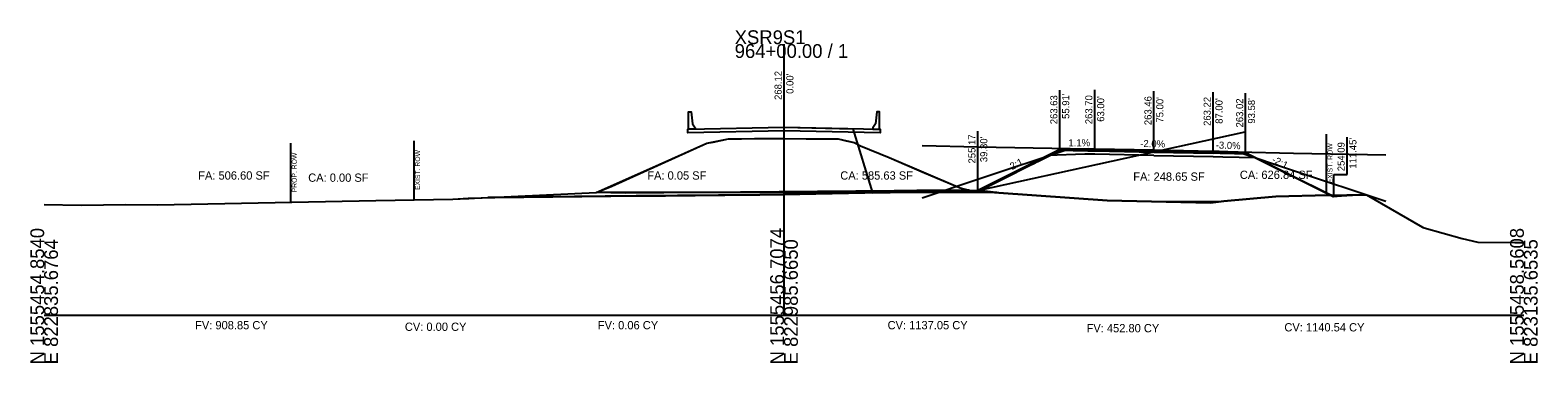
# Model space of a CAD drawing. Extents: x -26 to 823017, y -16 to 1558356.
# Drawn here: x 997.2 to 1302.8, y 3490.3 to 3557.8 of the extents above; entities that cross this region are included whole.
import ezdxf

# ---------------------------------------------------------------- set-up
doc = ezdxf.new("R2010")
doc.units = 0
for name, color, linetype in [('ASPHALT_19MM1', 7, 'Continuous'), ('CONST_DCH', 7, 'Continuous'), ('CONST_LV3', 7, 'Continuous'), ('Default', 7, 'Continuous'), ('Draft_XS_Grid', 7, 'Continuous'), ('DTM_CORRIDOR', 7, 'Continuous'), ('DTM_P_FINISHED_GRADE2', 7, 'Continuous'), ('DTM_TEMP_DROP', 7, 'Continuous'), ('DTM_X_GROUND', 7, 'Continuous'), ('PROFILES_DCH_2', 7, 'Continuous'), ('SLOPE_STAKES_FILL', 7, 'Continuous'), ('XS_CELL', 7, 'Continuous'), ('XS_M_SHAPES_EARTHWORK', 7, 'Continuous'), ('XS_P_ASPHALT', 7, 'Continuous'), ('XS_P_CONCRETE', 7, 'Continuous'), ('XS_P_DR_GRAVEL', 7, 'Continuous'), ('XS_P_GROUND', 7, 'Continuous'), ('XS_P_NULL_POINT', 7, 'Continuous'), ('XS_P_ROW', 7, 'Continuous'), ('XS_P_SHOULDER', 7, 'Continuous'), ('XS_P_SUBGRADE_GRANULAR', 7, 'Continuous'), ('XS_P_SUBGRADE_UNDERCUT', 7, 'Continuous'), ('XS_P_TX_CLEARZONE', 7, 'Continuous'), ('XS_P_TX_FS_BS', 7, 'Continuous'), ('XS_SHEET_EW_TX_AREA', 7, 'Continuous'), ('XS_SHEET_EW_TX_VOLUME', 7, 'Continuous'), ('XS_X_ROW', 7, 'Continuous')]:
    doc.layers.add(name, color=color, linetype=linetype)

msp = doc.modelspace()

# ---------------------------------------------------------------- linework, layer by layer
at = {"layer": 'ASPHALT_19MM1'}
msp.add_lwpolyline([(1213, 3533.33), (1225, 3533.09), (1237, 3532.85), (1237, 3533.05), (1225, 3533.29), (1213, 3533.53), (1213, 3533.33)], dxfattribs=at)
at = {"layer": 'CONST_DCH'}
msp.add_lwpolyline([(1213, 3533.53), (1225, 3533.29), (1237, 3533.05), (1237, 3533.22), (1225, 3533.46), (1213, 3533.7), (1213, 3533.53)], dxfattribs=at)
at = {"layer": 'CONST_LV3'}
for points in [[(1150, 3538.12), (1164, 3537.84)], [(1168, 3524.85), (1168, 3524.85), (1164, 3537.84)], [(1189.3, 3525.32), (1243.53, 3537.18), (1243.53, 3537.18)], [(1178, 3534.4), (1189.31, 3534.18), (1208, 3533.8), (1214.41, 3533.67), (1225, 3533.46), (1235.59, 3533.25), (1242, 3533.12), (1253.31, 3532.9), (1272, 3532.52)], [(1178, 3523.8), (1189.31, 3527.57), (1208, 3533.8), (1214.41, 3533.67), (1225, 3533.46), (1235.59, 3533.25), (1242, 3533.12), (1253.31, 3529.35), (1272, 3523.12)], [(1189.3, 3525.32), (1201.35, 3531.35), (1205.91, 3533.63), (1211.75, 3533.72), (1213, 3533.7)], [(1189.6, 3525.26), (1191.43, 3526.18), (1197.16, 3529.04), (1197.23, 3529.08), (1197.34, 3529.13), (1199.63, 3530.28), (1200.92, 3530.92), (1200.94, 3530.93), (1201.12, 3531.02), (1201.47, 3531.2), (1205.91, 3533.42), (1211.75, 3533.65), (1213, 3533.7), (1222.01, 3533.52), (1225, 3533.46), (1234.01, 3533.28), (1237, 3533.22), (1238.25, 3533.17), (1243.58, 3532.96), (1248.25, 3530.63), (1250.7, 3529.4), (1259.83, 3524.84), (1261.33, 3524.09), (1263, 3524.22), (1264.08, 3524.27), (1266.38, 3524.42), (1268.1, 3524.44), (1279.43, 3517.88), (1279.55, 3517.81), (1279.64, 3517.75), (1279.8, 3517.7), (1287.5, 3515.52), (1290.66, 3514.78), (1298.15, 3514.73), (1300, 3514.73)], [(1243.58, 3533.02), (1260.98, 3524.33)], [(1000, 3522.45), (1007.51, 3522.34), (1016.53, 3522.43), (1022.97, 3522.39), (1067.25, 3523.26), (1082.86, 3523.53), (1085.83, 3523.69), (1086.06, 3523.71), (1086.16, 3523.71), (1086.29, 3523.72), (1087.28, 3523.76), (1089.93, 3523.88)]]:
    msp.add_lwpolyline(points, dxfattribs=at)
at = {"layer": 'Default'}
msp.add_lwpolyline([(1187.49, 3525.35), (1187.19, 3525.34), (1176.92, 3525.26), (1175.41, 3525.24), (1172.34, 3525.22), (1117.88, 3524.78), (1111.93, 3524.86)], dxfattribs=at)
at = {"layer": 'DTM_P_FINISHED_GRADE2'}
msp.add_lwpolyline([(1089.93, 3523.88), (1090.73, 3523.89), (1091.01, 3523.89), (1091.35, 3523.89), (1114.88, 3524.13), (1120.33, 3524.18), (1126, 3524.24), (1150, 3524.48), (1156.45, 3524.63), (1189.6, 3525.26)], dxfattribs=at)
at = {"layer": 'DTM_X_GROUND'}
for points in [[(1000, 3522.45), (1007.51, 3522.34), (1016.53, 3522.43), (1022.97, 3522.39), (1067.25, 3523.26), (1082.86, 3523.53), (1086.06, 3523.71), (1086.16, 3523.71), (1087.28, 3523.76), (1090.35, 3523.9), (1111.93, 3524.86), (1115.08, 3526.2), (1134.32, 3534.88), (1135.67, 3535.12), (1138.77, 3535.8), (1144.04, 3535.82), (1149.78, 3535.84), (1159.14, 3535.76), (1160.97, 3535.75), (1160.97, 3535.75), (1162.57, 3535.4), (1164.2, 3535.03), (1165.49, 3534.39), (1171.33, 3532), (1185.7, 3525.82), (1187.67, 3525.3), (1193.53, 3524.83), (1215.49, 3523.25), (1236.44, 3522.77), (1239.16, 3523.13), (1249.74, 3524.05), (1260.36, 3524.34), (1264.08, 3524.39), (1268.1, 3524.44), (1279.43, 3517.88), (1279.55, 3517.81), (1279.64, 3517.75), (1279.8, 3517.7), (1287.5, 3515.52), (1290.66, 3514.78), (1298.15, 3514.73), (1300, 3514.73)], [(1000, 3522.45), (1007.51, 3522.34), (1016.53, 3522.43), (1022.97, 3522.39), (1067.25, 3523.26), (1082.86, 3523.53), (1086.06, 3523.71), (1086.16, 3523.71), (1087.28, 3523.76), (1090.35, 3523.9), (1111.93, 3524.86), (1115.08, 3526.2), (1134.32, 3534.88), (1135.67, 3535.12), (1138.77, 3535.8), (1144.04, 3535.82), (1149.78, 3535.84), (1159.14, 3535.76), (1160.97, 3535.75), (1160.97, 3535.75), (1162.57, 3535.4), (1164.2, 3535.03), (1165.49, 3534.39), (1171.33, 3532), (1185.7, 3525.82), (1187.49, 3525.35), (1187.67, 3525.34), (1189.6, 3525.26), (1197.34, 3529.13), (1201.12, 3531.02), (1201.47, 3531.2), (1205.91, 3533.42), (1211.75, 3533.65), (1213, 3533.7), (1222.01, 3533.52), (1225, 3533.46), (1234.01, 3533.28), (1237, 3533.22), (1238.25, 3533.17), (1243.58, 3532.96), (1248.25, 3530.63), (1250.7, 3529.4), (1259.83, 3524.84), (1261.33, 3524.09), (1263, 3524.22), (1264.08, 3524.27), (1266.38, 3524.42), (1268.1, 3524.44), (1279.43, 3517.88), (1279.55, 3517.81), (1279.64, 3517.75), (1279.8, 3517.7), (1287.5, 3515.52), (1290.66, 3514.78), (1298.15, 3514.73), (1300, 3514.73)], [(1000, 3522.45), (1007.51, 3522.34), (1016.53, 3522.43), (1022.97, 3522.39), (1067.25, 3523.26), (1082.86, 3523.53), (1085.83, 3523.69), (1086.06, 3523.7), (1086.16, 3523.71), (1086.29, 3523.72), (1087.28, 3523.76), (1089.93, 3523.88), (1090.2, 3523.88), (1090.29, 3523.88), (1090.63, 3523.89), (1090.73, 3523.89), (1090.8, 3523.89), (1090.86, 3523.89), (1091.01, 3523.89), (1091.35, 3523.89), (1114.88, 3524.13), (1120.33, 3524.18), (1126, 3524.24), (1150, 3524.48), (1156.45, 3524.63), (1189.6, 3525.26), (1191.43, 3526.18), (1197.16, 3529.04), (1197.23, 3529.08), (1197.34, 3529.13), (1199.63, 3530.28), (1200.92, 3530.92), (1200.94, 3530.93), (1201.12, 3531.02), (1201.47, 3531.2), (1205.91, 3533.42), (1211.75, 3533.65), (1213, 3533.7), (1222.01, 3533.52), (1225, 3533.46), (1234.01, 3533.28), (1237, 3533.22), (1238.25, 3533.17), (1243.58, 3532.96), (1248.25, 3530.63), (1250.7, 3529.4), (1259.83, 3524.84), (1261.33, 3524.09), (1263, 3524.22), (1264.08, 3524.27), (1266.38, 3524.42), (1268.1, 3524.44), (1279.43, 3517.88), (1279.55, 3517.81), (1279.64, 3517.75), (1279.8, 3517.7), (1287.5, 3515.52), (1290.66, 3514.78), (1298.15, 3514.73), (1300, 3514.73)]]:
    msp.add_lwpolyline(points, dxfattribs=at)
at = {"layer": 'XS_CELL'}
for p, q in [((1150, 3500), (1150, 3555)), ((1000, 3500), (1150, 3500)), ((1150, 3500), (1300, 3500))]:
    msp.add_line(p, q, dxfattribs=at)
at = {"layer": 'XS_M_SHAPES_EARTHWORK'}
for points in [[(1089.93, 3523.88), (1090.35, 3523.9), (1111.93, 3524.86), (1115.08, 3526.2), (1134.32, 3534.88), (1135.67, 3535.12), (1138.77, 3535.8), (1144.04, 3535.82), (1149.78, 3535.84), (1159.14, 3535.76), (1160.97, 3535.75), (1160.97, 3535.75), (1162.57, 3535.4), (1164.2, 3535.03), (1165.49, 3534.39), (1171.33, 3532), (1185.7, 3525.82), (1187.67, 3525.3), (1188.25, 3525.25), (1156.41, 3524.63), (1150, 3524.48), (1145.1, 3524.43), (1120, 3524.18), (1094.94, 3523.93)], [(1188.25, 3525.25), (1189.3, 3525.17), (1189.3, 3525.27)]]:
    msp.add_lwpolyline(points, close=True, dxfattribs=at)
at = {"layer": 'XS_P_CONCRETE'}
for points in [[(1130.67, 3537.74), (1130.67, 3541.24), (1131.17, 3541.26), (1131.42, 3538.85), (1132, 3538.01), (1132, 3537.76), (1130.67, 3537.74)], [(1169.33, 3537.74), (1169.33, 3541.24), (1168.83, 3541.26), (1168.58, 3538.85), (1168, 3538.01), (1168, 3537.76), (1169.33, 3537.74)], [(1150, 3538.12), (1169.33, 3537.74), (1169.5, 3537.73), (1169.5, 3536.98), (1150, 3537.37), (1130.5, 3536.98), (1130.5, 3537.73), (1130.67, 3537.74), (1150, 3538.12)]]:
    msp.add_lwpolyline(points, dxfattribs=at)
at = {"layer": 'XS_P_DR_GRAVEL'}
for points in [[(1211.75, 3533.72), (1205.91, 3533.63), (1205.75, 3533.54), (1205.61, 3533.47), (1211.59, 3533.35), (1213, 3533.33), (1213, 3533.61), (1213, 3533.7), (1211.75, 3533.72)], [(1238.25, 3533.19), (1243.58, 3533.02), (1243.77, 3532.93), (1244.23, 3532.7), (1238.44, 3532.82), (1237, 3532.85), (1237, 3533.13), (1237, 3533.22), (1238.25, 3533.19)]]:
    msp.add_lwpolyline(points, dxfattribs=at)
at = {"layer": 'XS_P_GROUND'}
for points in [[(1205.91, 3533.63), (1189.3, 3525.32)], [(1243.58, 3533.02), (1261.45, 3524.09)], [(1189.3, 3525.27), (1156.41, 3524.63), (1150, 3524.48)], [(1168, 3524.85), (1189.3, 3525.25), (1189.3, 3525.25)], [(1168, 3524.85), (1189.3, 3525.25), (1189.3, 3525.25)], [(1260.98, 3524.35), (1260.36, 3524.34), (1260.36, 3524.34), (1249.74, 3524.05), (1249.74, 3524.05), (1239.16, 3523.13), (1239.16, 3523.13), (1236.44, 3522.77), (1236.44, 3522.77), (1215.49, 3523.25), (1215.49, 3523.25), (1193.53, 3524.83), (1193.53, 3524.83), (1189.3, 3525.17)], [(1189.3, 3525.17), (1193.53, 3524.83), (1193.53, 3524.83), (1215.49, 3523.25), (1215.49, 3523.25), (1236.44, 3522.77), (1236.44, 3522.77), (1239.16, 3523.13), (1239.16, 3523.13), (1249.74, 3524.05), (1249.74, 3524.05), (1260.36, 3524.34), (1260.36, 3524.34), (1260.98, 3524.35)], [(1089.93, 3523.88), (1094.94, 3523.93), (1120, 3524.18)], [(1120, 3524.18), (1145.1, 3524.43), (1150, 3524.48)]]:
    msp.add_lwpolyline(points, dxfattribs=at)
at = {"layer": 'XS_P_ROW'}
msp.add_line((1050, 3522.92), (1050, 3534.92), dxfattribs=at)
at = {"layer": 'XS_P_SHOULDER'}
for points in [[(1205.91, 3533.63), (1211.75, 3533.72), (1213, 3533.7)], [(1243.58, 3533.02), (1238.25, 3533.19), (1237, 3533.22)]]:
    msp.add_lwpolyline(points, dxfattribs=at)
at = {"layer": 'XS_P_SUBGRADE_GRANULAR'}
for points in [[(1213, 3532.66), (1211, 3532.7), (1203.46, 3532.4)], [(1225, 3532.42), (1213, 3532.66)], [(1225, 3532.42), (1237, 3532.18)], [(1237, 3532.18), (1239, 3532.14), (1245.62, 3532.01)]]:
    msp.add_lwpolyline(points, dxfattribs=at)
at = {"layer": 'XS_P_SUBGRADE_UNDERCUT'}
for points in [[(1111.93, 3524.86), (1124.7, 3530.54), (1134.32, 3534.88), (1138.77, 3535.8), (1141.4, 3535.81), (1146.91, 3535.83), (1149.78, 3535.84), (1154.46, 3535.8), (1159.14, 3535.76), (1160.97, 3535.75), (1164.2, 3535.03), (1165.49, 3534.39), (1171.33, 3532), (1178.51, 3528.91), (1185.7, 3525.82), (1187.67, 3525.3), (1190.6, 3525.06), (1193.14, 3524.86)], [(1226.45, 3523), (1215.49, 3523.25), (1204.51, 3524.04), (1193.53, 3524.83), (1189.6, 3525.26), (1205.91, 3533.42), (1213, 3533.7), (1225, 3533.46), (1237, 3533.22), (1243.58, 3532.96), (1260.81, 3524.34), (1255.05, 3524.2), (1249.74, 3524.05), (1244.45, 3523.59), (1239.16, 3523.13), (1238.17, 3523)]]:
    msp.add_lwpolyline(points, close=True, dxfattribs=at)
at = {"layer": 'XS_P_TX_CLEARZONE'}
for p, q in [((1150, 3538.12), (1150, 3550.12)), ((1205.91, 3533.63), (1205.91, 3545.63)), ((1213, 3533.7), (1213, 3545.7)), ((1225, 3533.46), (1225, 3545.46)), ((1237, 3533.22), (1237, 3545.22)), ((1243.58, 3533.02), (1243.58, 3545.02)), ((1189.3, 3525.32), (1189.3, 3537.32)), ((1264.15, 3528.52), (1264.15, 3536.09)), ((1261.45, 3524.09), (1261.45, 3528.52)), ((1261.45, 3528.52), (1264.15, 3528.52))]:
    msp.add_line(p, q, dxfattribs=at)
at = {"layer": 'XS_X_ROW'}
for p, q in [((1260, 3524.75), (1260, 3536.75)), ((1075, 3523.39), (1075, 3535.39))]:
    msp.add_line(p, q, dxfattribs=at)

# ---------------------------------------------------------------- texts
at = {"layer": 'CONST_DCH'}
for p in [(1189.22, 3525.2), (1260.9, 3524.21), (1261.37, 3523.97)]:
    msp.add_text('X', height=0.24, dxfattribs=at).set_placement(p)
at = {"layer": 'Draft_XS_Grid'}
msp.add_text('-', height=0.0001, dxfattribs=at).set_placement((1000, 3500))
at = {"layer": 'DTM_CORRIDOR'}
for p in [(1212.92, 3533.58), (1224.92, 3533.34), (1236.92, 3533.1)]:
    msp.add_text('X', height=0.24, dxfattribs=at).set_placement(p)
at = {"layer": 'DTM_TEMP_DROP'}
for p in [(1149.92, 3538), (1189.22, 3525.05)]:
    msp.add_text('X', height=0.24, dxfattribs=at).set_placement(p)
at = {"layer": 'PROFILES_DCH_2'}
for p in [(1167.92, 3524.73), (1189.22, 3525.2), (1260.9, 3524.21)]:
    msp.add_text('X', height=0.24, dxfattribs=at).set_placement(p)
at = {"layer": 'SLOPE_STAKES_FILL'}
for p in [(1149.92, 3524.36), (1189.22, 3525.15), (1089.85, 3523.76)]:
    msp.add_text('X', height=0.24, dxfattribs=at).set_placement(p)
at = {"layer": 'XS_CELL'}
for s, p in [('XSR9S1', (1140, 3555)), ('964+00.00 / 1', (1140, 3552.2))]:
    msp.add_text(s, height=2.8, dxfattribs=at).set_placement(p)
for s, p in [('N 1555454.8540', (1000, 3490)), ('N 1555456.7074', (1150, 3490)), ('N 1555458.5608', (1300, 3490)), ('E 822835.6764', (1002.8, 3490)), ('E 822985.6650', (1152.8, 3490)), ('E 823135.6535', (1302.8, 3490))]:
    msp.add_text(s, height=2.8, rotation=90, dxfattribs=at).set_placement(p)
at = {"layer": 'XS_P_ASPHALT'}
for p in [(1189.22, 3525.2), (1261.37, 3523.97)]:
    msp.add_text('X', height=0.24, dxfattribs=at).set_placement(p)
at = {"layer": 'XS_P_NULL_POINT'}
msp.add_text('X', height=0.24, dxfattribs=at).set_placement((1189.22, 3525.15))
at = {"layer": 'XS_P_ROW'}
msp.add_text('PROP. ROW', height=1, rotation=90, dxfattribs=at).set_placement((1051.2, 3524.92))
at = {"layer": 'XS_P_SHOULDER'}
for p in [(1205.84, 3533.51), (1243.51, 3532.9), (1149.92, 3524.36)]:
    msp.add_text('X', height=0.24, dxfattribs=at).set_placement(p)
at = {"layer": 'XS_P_TX_CLEARZONE'}
for s, p in [('268.12', (1149.52, 3543.67)), ("0.00'", (1151.92, 3544.91)), ('263.63', (1205.43, 3538.74)), ("55.91'", (1207.83, 3539.82)), ('263.70', (1212.52, 3538.75)), ("63.00'", (1214.92, 3539.24)), ('263.46', (1224.52, 3538.56)), ("75.00'", (1226.92, 3539.07)), ('263.22', (1236.52, 3538.4)), ("87.00'", (1238.92, 3538.83)), ('263.02', (1243.1, 3538.09)), ("93.58'", (1245.5, 3538.86)), ('255.17', (1188.82, 3530.78)), ("39.30'", (1191.22, 3531.04)), ('254.09', (1263.67, 3529.21)), ("111.45'", (1266.07, 3529.72))]:
    msp.add_text(s, height=1.44, rotation=90, dxfattribs=at).set_placement(p)
at = {"layer": 'XS_P_TX_FS_BS'}
for s, rotation, p in [('1.1%', 0.6144, (1207.67, 3534.24)), ('-2.0%', 358.8542, (1222.22, 3534.12)), ('-3.0%', 358.2755, (1237.52, 3533.81)), ('2:1', 26.6898, (1196.24, 3529.43)), ('-2:1', 333.4349, (1248.78, 3531.1))]:
    msp.add_text(s, height=1.44, rotation=rotation, dxfattribs=at).set_placement(p)
at = {"layer": 'XS_SHEET_EW_TX_AREA'}
for s, p in [('FA: 506.60 SF', (1031.23, 3527.5)), ('CA: 0.00 SF', (1053.53, 3527.06)), ('FA: 0.05 SF', (1122.28, 3527.5)), ('CA: 585.63 SF', (1161.41, 3527.5)), ('FA: 248.65 SF', (1220.81, 3527.27)), ('CA: 626.84 SF', (1242.42, 3527.64))]:
    msp.add_text(s, height=1.68, dxfattribs=at).set_placement(p)
at = {"layer": 'XS_SHEET_EW_TX_VOLUME'}
for s, p in [('FV: 908.85 CY', (1030.6, 3497.12)), ('CV: 0.00 CY', (1073.13, 3496.8)), ('FV: 0.06 CY', (1112.25, 3497.12)), ('CV: 1137.05 CY', (1171, 3497.12)), ('FV: 452.80 CY', (1211.35, 3496.51)), ('CV: 1140.54 CY', (1251.45, 3496.69))]:
    msp.add_text(s, height=1.68, dxfattribs=at).set_placement(p)
at = {"layer": 'XS_X_ROW'}
for p in [(1261.2, 3526.75), (1076.2, 3525.39)]:
    msp.add_text('EXIST. ROW', height=1, rotation=90, dxfattribs=at).set_placement(p)

doc.saveas('drawing.dxf')
